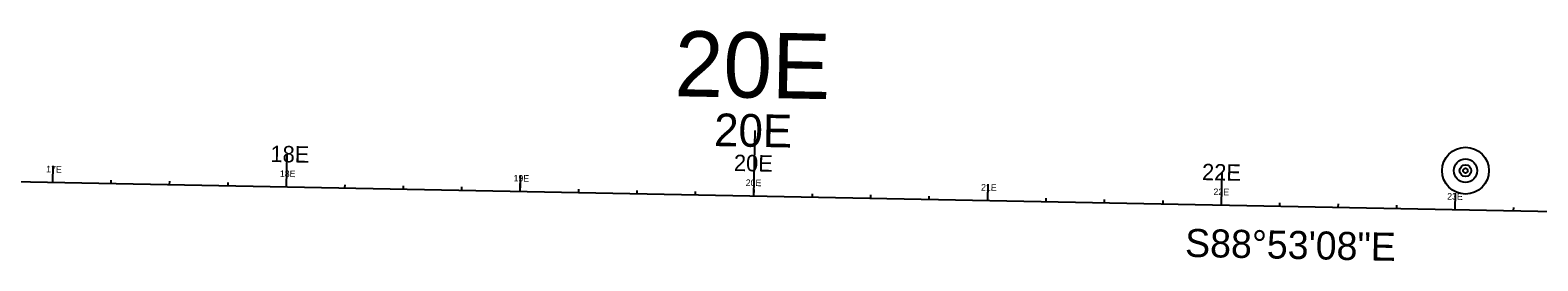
# Model space of a CAD drawing. Extents: x 593604 to 599725, y 225853 to 238227.
# Drawn here: x 595304 to 595949, y 231085 to 231184 of the extents above; entities that cross this region are included whole.
import ezdxf

# ---------------------------------------------------------------- set-up
doc = ezdxf.new("R2010")
doc.units = 0
for name, color, linetype in [('P_ALI_100', 7, 'Continuous'), ('P_ALI_100_Equation', 7, 'Continuous'), ('P_ALI_100_Sta', 7, 'Continuous'), ('P_ALI_100_Tic', 7, 'Continuous'), ('P_ALI_100_TPI', 7, 'Continuous'), ('P_ALI_20', 7, 'Continuous'), ('P_ALI_200', 7, 'Continuous'), ('P_ALI_200_Sta', 7, 'Continuous'), ('P_ALI_200_Tic', 7, 'Continuous'), ('P_ALI_200_TPI', 7, 'Continuous'), ('P_ALI_20_Sta', 7, 'Continuous'), ('P_ALI_20_Tic', 7, 'Continuous'), ('P_ALI_20_TPI', 7, 'Continuous'), ('P_ALI_50', 7, 'Continuous'), ('P_ALI_50_Sta', 7, 'Continuous'), ('P_ALI_50_Tic', 7, 'Continuous'), ('P_ALI_50_TPI', 7, 'Continuous')]:
    doc.layers.add(name, color=color, linetype=linetype)

msp = doc.modelspace()

# ---------------------------------------------------------------- linework, layer by layer
at = {"layer": 'P_ALI_100'}
msp.add_line((594613.51, 231132.06), (597030.01, 231085.05), dxfattribs=at)
at = {"layer": 'P_ALI_100_Tic'}
for points in [[(595613.59, 231126.61), (595613.32, 231112.61)], [(595313.51, 231125.44), (595313.38, 231118.44)], [(595413.49, 231123.5), (595413.36, 231116.5)], [(595513.48, 231121.55), (595513.34, 231114.55)], [(595713.44, 231117.66), (595713.3, 231110.66)], [(595813.42, 231115.72), (595813.28, 231108.72)], [(595913.4, 231113.77), (595913.26, 231106.77)]]:
    msp.add_lwpolyline(points, dxfattribs=at)
at = {"layer": 'P_ALI_100_TPI'}
msp.add_circle((595917.82, 231123.41), 5, dxfattribs=at)
at = {"layer": 'P_ALI_20'}
msp.add_line((594613.51, 231132.06), (597030.01, 231085.05), dxfattribs=at)
at = {"layer": 'P_ALI_200'}
msp.add_line((594613.51, 231132.06), (597030.01, 231085.05), dxfattribs=at)
at = {"layer": 'P_ALI_200_Tic'}
for points in [[(595613.87, 231140.6), (595613.32, 231112.61)], [(595413.63, 231130.5), (595413.36, 231116.5)], [(595813.56, 231122.72), (595813.28, 231108.72)]]:
    msp.add_lwpolyline(points, dxfattribs=at)
at = {"layer": 'P_ALI_200_TPI'}
msp.add_circle((595917.82, 231123.41), 10, dxfattribs=at)
at = {"layer": 'P_ALI_20_Tic'}
for points in [[(595313.43, 231121.24), (595313.38, 231118.44)], [(595338.4, 231119.36), (595338.37, 231117.96)], [(595363.4, 231118.87), (595363.37, 231117.47)], [(595388.39, 231118.39), (595388.36, 231116.99)], [(595413.41, 231119.3), (595413.36, 231116.5)], [(595438.38, 231117.41), (595438.35, 231116.01)], [(595463.38, 231116.93), (595463.35, 231115.53)], [(595488.37, 231116.44), (595488.34, 231115.04)], [(595513.39, 231117.35), (595513.34, 231114.55)], [(595538.36, 231115.47), (595538.34, 231114.07)], [(595563.36, 231114.98), (595563.33, 231113.58)], [(595588.35, 231114.5), (595588.33, 231113.1)], [(595613.38, 231115.41), (595613.32, 231112.61)], [(595638.34, 231113.52), (595638.32, 231112.12)], [(595713.36, 231113.46), (595713.3, 231110.66)], [(595663.34, 231113.04), (595663.31, 231111.64)], [(595688.33, 231112.55), (595688.31, 231111.15)], [(595738.32, 231111.58), (595738.3, 231110.18)], [(595763.32, 231111.09), (595763.29, 231109.69)], [(595788.31, 231110.61), (595788.29, 231109.21)], [(595813.34, 231111.52), (595813.28, 231108.72)], [(595838.31, 231109.63), (595838.28, 231108.23)], [(595863.3, 231109.15), (595863.27, 231107.75)], [(595888.3, 231108.66), (595888.27, 231107.26)], [(595913.32, 231109.57), (595913.26, 231106.77)], [(595938.29, 231107.69), (595938.26, 231106.29)]]:
    msp.add_lwpolyline(points, dxfattribs=at)
at = {"layer": 'P_ALI_20_TPI'}
msp.add_circle((595917.82, 231123.41), 1, dxfattribs=at)
at = {"layer": 'P_ALI_50'}
msp.add_line((594613.51, 231132.06), (597030.01, 231085.05), dxfattribs=at)
at = {"layer": 'P_ALI_50_Tic'}
for points in [[(595313.45, 231121.94), (595313.38, 231118.44)], [(595413.49, 231123.5), (595413.36, 231116.5)], [(595513.41, 231118.05), (595513.34, 231114.55)], [(595613.46, 231119.61), (595613.32, 231112.61)], [(595713.37, 231114.16), (595713.3, 231110.66)], [(595813.42, 231115.72), (595813.28, 231108.72)], [(595913.33, 231110.27), (595913.26, 231106.77)]]:
    msp.add_lwpolyline(points, dxfattribs=at)
at = {"layer": 'P_ALI_50_TPI'}
msp.add_circle((595917.82, 231123.41), 2.5, dxfattribs=at)

# ---------------------------------------------------------------- texts
for p in [(595313.24, 231118.45), (595513.2, 231114.56), (595713.16, 231110.67), (595913.12, 231106.78)]:
    msp.add_text('0E', height=0.14, rotation=268.88552).set_placement(p)
at = {"layer": 'P_ALI_100_Equation'}
msp.add_text('S88%%d53\'08"E', height=12, rotation=358.88552, dxfattribs=at).set_placement((595797.79, 231086.54))
at = {"layer": 'P_ALI_100_Sta'}
msp.add_text('20E', height=14, rotation=358.88552, dxfattribs=at).set_placement((595596.32, 231133.94))
at = {"layer": 'P_ALI_200_Sta'}
msp.add_text('20E', height=28, rotation=358.88552, dxfattribs=at).set_placement((595579.31, 231155.28))
at = {"layer": 'P_ALI_20_Sta'}
for s, p in [('17E', (595310.66, 231122.7)), ('18E', (595410.64, 231120.75)), ('19E', (595510.6, 231118.81)), ('20E', (595609.92, 231116.88)), ('21E', (595710.58, 231114.92)), ('22E', (595809.99, 231112.98)), ('23E', (595909.97, 231111.04))]:
    msp.add_text(s, height=2.8, rotation=358.88552, dxfattribs=at).set_placement(p)
at = {"layer": 'P_ALI_50_Sta'}
for s, p in [('18E', (595406.56, 231127.13)), ('20E', (595604.82, 231123.28)), ('22E', (595805.06, 231119.38))]:
    msp.add_text(s, height=7, rotation=358.88552, dxfattribs=at).set_placement(p)

doc.saveas('drawing.dxf')
